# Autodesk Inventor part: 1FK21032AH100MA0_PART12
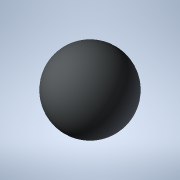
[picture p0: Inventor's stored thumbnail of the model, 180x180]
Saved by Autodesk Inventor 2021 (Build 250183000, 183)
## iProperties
Created: 2025-04
Part Number: 1FK21032AH100MA0_PART12
Material: Generic
Catalog Web Link: www.3dfindit.com
Description: -Servo synchronous motor
Document SubType Name: Modeling
Designer: psAdmin
Mass: 0.113097 g
Surface Area: 1.13097 cm^2
Volume: 0.113097 cm^3
Density: 1 g/cm^3
Appearance: PSOLRGB-212-217-219
Category: PARTsolutions
Title: 1FK21032AH100MA0_PART12
Author: Cadenas PARTsolutions
Comments: Servo synchronous motor
Sending System: PARTsolutions
Preprocessor: ST-DEVELOPER v19.3
PSOL_IDENT_0: {$CADENAS_DATA/23d-libs/siemens_ag/_cat_/12/33/1fk21032ah100ma0.prj},216 {VTYP=3D},{NB=1FK21032AH100
PSOL_IDENT_1: MA0_PART12},{LINA=1FK21032AH100MA0_PART12},{NN=1FK21032AH100MA0_PART12},{NOPRJ=TRUE},{DATE=19.08.202
PSOL_IDENT_2: 5 14:00:27},{GEOMDATE=30.07.2025 02:02:58},{VERSION=},{LINEID=10},{WBVAR=},{WBNUMERIC=}  {NB=1FK2103
PSOL_IDENT_3: 2AH100MA0_PART12},{LINA=1FK21032AH100MA0_PART12},{KT=DUMMY},{PREVIEW=../../../_pool_/d3/78/p_d211_xx
PSOL_IDENT_4: _00934j.png},{DESCSHORT=SIMOTICS S-1FK2 HD, SINAMICS S210 3AC 400V-480V, 0.59 Nm, 4500 rpm},{DESCLON
PSOL_IDENT_5: G=SIMOTICS S-1FK2 HD servo motor M0=0.64 Nm; PN = 0.28 kW at nN=4500 rpm (380-480 V); PN = 0.167 kW
PSOL_IDENT_6: at nN=2500 rpm (200-240 V); with holding brake; degree of protection IP64; cylindrical shaft D14 x 3
PSOL_IDENT_7: 0 mm; absolute encoder 22-bit + 12-bit multiturn (encoder AM22DQC); with OCC interface; plug size M1
PSOL_IDENT_8: 7, rotatable; SIMOTICS S-1FK2 servomotorfor a wide range of uses in industrial environments. SIMOTIC
PSOL_IDENT_9: S S‑1FK2 servomotors are compact synchronous motors with a high dynamic performance that set themsel
PSOL_IDENT_10: ves apart as a result of their high power density, degree of protection and overload capability. The
PSOL_IDENT_11: motors are available in two variants: as High Dynamic variant (highest dynamic performance as a res
PSOL_IDENT_12: ult of the low intrinsic moment of inertia for applications demanding a high dynamic performance wit
PSOL_IDENT_13: h low moved masses) - and as Compact variant (precise and stable closed-loop control for medium up t
PSOL_IDENT_14: o large moved masses as a result of a medium intrinsic moment of inertia). SIMOTICSS‑1FK2 servomotor
PSOL_IDENT_15: s fully exploit their strengths in a system with the SINAMICSS210 frequency converter and simple con
PSOL_IDENT_16: nection using the one cable connection (OCC). Advantages include the short control and positioning t
PSOL_IDENT_17: imes, fast and precise correction of disturbing quantities as well as stable control with a high dyn
PSOL_IDENT_18: amic performance. The servo motors can be configured to address a wide range of requirements. For ex
PSOL_IDENT_19: ample with and without holding brake, IP64 or IP65 degree of protection, singleturn or multiturn abs
PSOL_IDENT_20: olute encoders - to name just a few. Further, the servomotors are available in different shaft heigh
PSOL_IDENT_21: ts extending from 20 to 100. A shaft sealing ring is available to achieve an IP65 degree of protecti
PSOL_IDENT_22: on and for subsequent mounting at the motor or as spare part. SIMOTICS - the optimum motor for each
PSOL_IDENT_23: and every motion control application.},{INTNO=195125315563},{SUPPLIERALTNO=1FK2103-2AH10-0MA0},{MANU
PSOL_IDENT_24: ID=1FK21032AH100MA0},{MANUNAME=Siemens},{MANUTYPEDESC=SYNCHRONOUS MOTOR 1FK2 HD 0,64 NM},{AAU732=SIM
PSOL_IDENT_25: OTICS},{AAO057=S-1FK2},{AAU734=SIMOTICS S-1FK2 HD servo motor M0=0.64 Nm; PN = 0.28 kW at nN=4500 rp
PSOL_IDENT_26: m (380-480 V); PN = 0.167 kW at nN=2500 rpm (200-240 V); with holding brake; degree of protection IP
PSOL_IDENT_27: 64; cylindrical shaft D14 x 30 mm; absolute encoder 22-bit + 12-bit multiturn (encoder AM22DQC); wit
PSOL_IDENT_28: h OCC interface; plug size M17, rotatable;},{AAW338=SYNCHRONOUS MOTOR 1FK2 HD 0,64 NM},{AAO742=SIMOT
PSOL_IDENT_29: ICS},{AAO663=4034106444723},{NOCUPEROU=1},{PRICEQUANTITY=1},{QUANTITYMIN=1},{QUANTITYINT=1},{CTN=850
PSOL_IDENT_30: 15100},{COO=RO},{AAO676=1FK2103-2AH10-0MA0},{AAO677=Siemens AG},{ORDERUNIT=C62},{CONTENTUNIT=C62}
NB: 1FK21032AH100MA0_PART12
NT: Servo synchronous motor
NBSYN: $MANUID._PART12
LINA: 1FK21032AH100MA0_PART12
CATALOG: SIEMENS
PREVIEW: ../../../_pool_/d3/78/p_d211_xx_00934j.png
DESCSHORT: SIMOTICS S-1FK2 HD, SINAMICS S210 3AC 400V-480V, 0.59 Nm, 4500 rpm
DESCLONG: SIMOTICS S-1FK2 HD servo motor M0=0.64 Nm; PN = 0.28 kW at nN=4500 rpm (380-480 V); PN = 0.167 kW at nN=2500 rpm (200-240 V); with holding brake; degree of prot
INTNO: 195125315563
SUPPLIERALTNO: 1FK2103-2AH10-0MA0
MANUID: 1FK21032AH100MA0
MANUNAME: Siemens
MANUTYPEDESC: SYNCHRONOUS MOTOR 1FK2 HD 0,64 NM
AAU732: SIMOTICS
AAO057: S-1FK2
AAU734: SIMOTICS S-1FK2 HD servo motor M0=0.64 Nm; PN = 0.28 kW at nN=4500 rpm (380-480 V); PN = 0.167 kW at nN=2500 rpm (200-240 V); with holding brake; degree of prot
AAW338: SYNCHRONOUS MOTOR 1FK2 HD 0,64 NM
AAO742: SIMOTICS
AAO663: 4034106444723.0
NOCUPEROU: 1
PRICEQUANTITY: 1
QUANTITYMIN: 1
QUANTITYINT: 1
CTN: 85015100
COO: RO
ARTICLENO: 1FK21032AH100MA0_PART12
BOMINFO: 1FK21032AH100MA0_PART12
CREATOR: CADENAS GmbH
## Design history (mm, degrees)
feature "2025_04_17_15_06_16_0705"
body "Solid1"
